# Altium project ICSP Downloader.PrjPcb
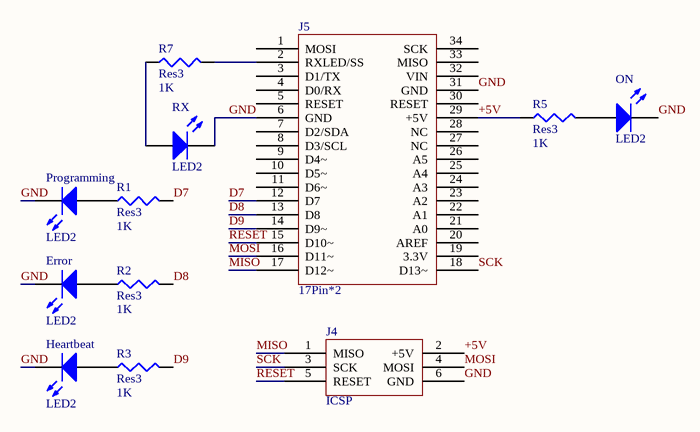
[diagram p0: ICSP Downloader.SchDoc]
1 sheet, 12 parts. Net scope: global (net labels, ports and power ports of the same name join across sheets).
Board file: ICSP Downloader v0.4.PcbDoc

## Sheet ICSP Downloader.SchDoc
size A4

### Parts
Error  LED2  [LED_0805]
Heartbeat  LED2  [LED_0805]
J4  ICSP  [ICSP]
J5  17Pin*2  [17Pin*2]
ON  LED2  [LED_0805]
Programming  LED2  [LED_0805]
R1  Res3  value 1K  [R0402]
R2  Res3  value 1K  [R0402]
R3  Res3  value 1K  [R0402]
R5  Res3  value 1K  [R0402]
R7  Res3  value 1K  [R0402]
RX  LED2  [LED_0805]

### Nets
+5V: J4.2(+5V) J5.29(+5V) R5.1
D7: J5.12(D7) R1.2
D8: J5.13(D8) R2.2
D9: J5.14(D9~) R3.2
GND: Error.2(K) Heartbeat.2(K) J4.6(GND) J5.6(GND) J5.31(GND) ON.2(K) Programming.2(K) RX.2(K)
MISO: J4.1(MISO) J5.17(D12~)
MOSI: J4.4(MOSI) J5.16(D11~)
RESET: J4.5(RESET) J5.15(D10~)
SCK: J4.3(SCK) J5.18(D13~)
NetError_1: Error.1(A) R2.1
NetHeartbeat_1: Heartbeat.1(A) R3.1
NetJ5_2: J5.2(RXLED/SS) R7.2
NetON_1: ON.1(A) R5.2
NetProgramming_1: Programming.1(A) R1.1
NetR7_1: R7.1 RX.1(A)

Not connected (* = marked no-connect by the designer): J5 1(MOSI) 3(D1/TX) 4(D0/RX) 5(RESET) 7(D2/SDA) 8(D3/SCL) 9(D4~) 10(D5~) 11(D6~) 19(3.3V) 20(AREF) 21(A0) 22(A1) 23(A2) 24(A3) 25(A4) 26(A5) 27(NC) 28(NC) 30(RESET) 32(VIN) 33(MISO) 34(SCK)

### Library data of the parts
Error Heartbeat ON Programming RX = LED2: Typical RED, GREEN, YELLOW, AMBER GaAs LED
J4 = ICSP: 2.54
J5 = 17Pin*2: Arduino Micro
R1-R3 R5 R7 = Res3: Resistor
